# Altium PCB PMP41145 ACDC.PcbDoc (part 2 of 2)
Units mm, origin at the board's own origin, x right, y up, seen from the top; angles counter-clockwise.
Board outline 48.82 x 27.36 mm, 2 copper layers (Top Layer, Bottom Layer), stack 1.016 mm thick; 61 components, 40 nets, 174 pads, 389 vias.
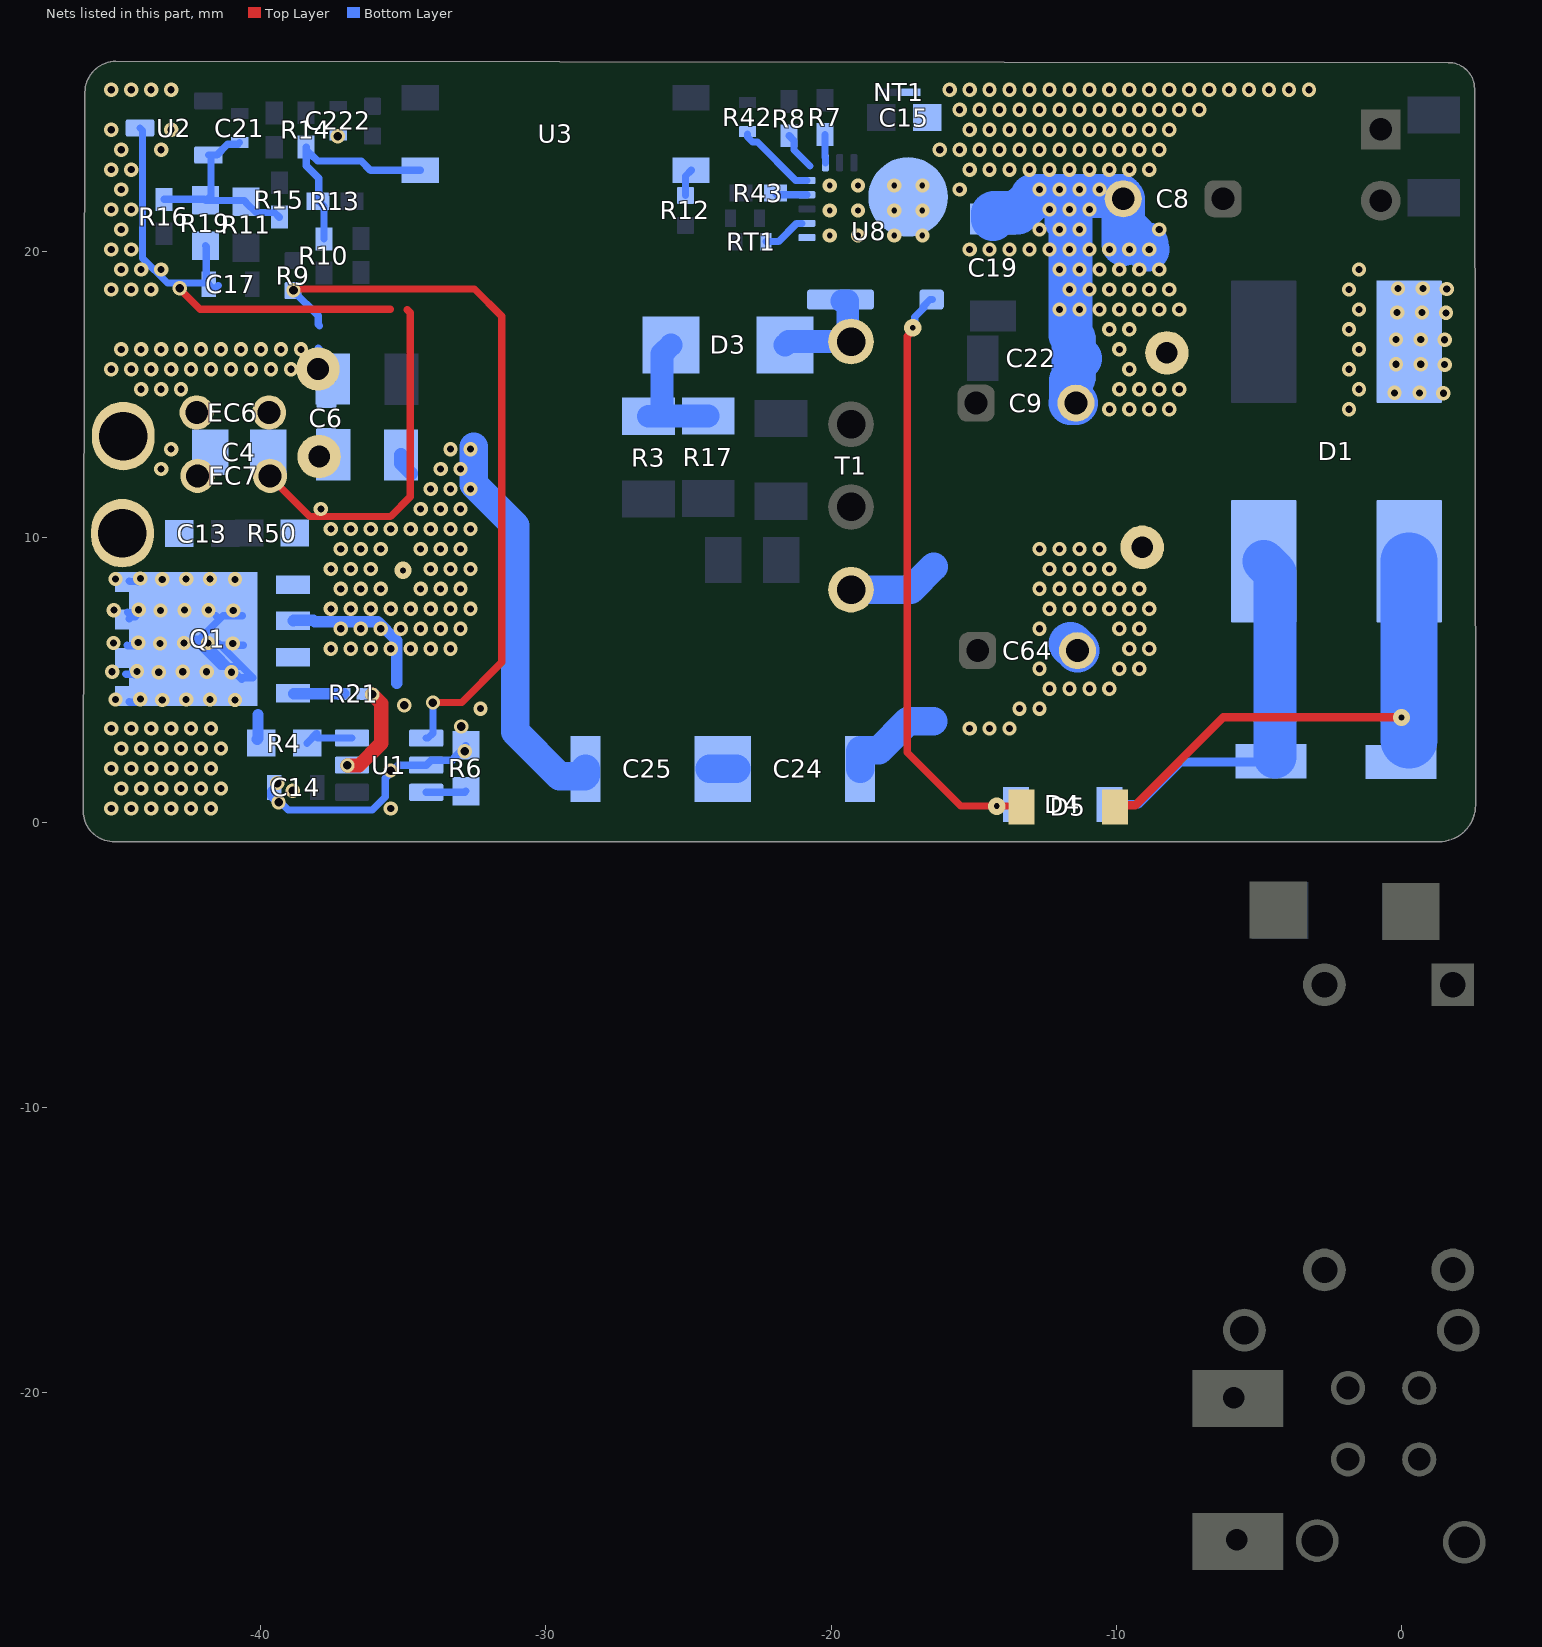
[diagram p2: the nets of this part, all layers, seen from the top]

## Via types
v1: diameter 0.5, hole 0.25, Top Layer to Bottom Layer, 301 vias
v2: diameter 0.5, hole 0.25, Top Layer to Bottom Layer, tented both sides, 45 vias
v3: diameter 0.61, hole 0.203, Top Layer to Bottom Layer, tented both sides, 16 vias
v4: diameter 0.5, hole 0.3, Top Layer to Bottom Layer, tented both sides, 15 vias
v5: diameter 0.5, hole 0.2, Top Layer to Bottom Layer, tented both sides, 12 vias

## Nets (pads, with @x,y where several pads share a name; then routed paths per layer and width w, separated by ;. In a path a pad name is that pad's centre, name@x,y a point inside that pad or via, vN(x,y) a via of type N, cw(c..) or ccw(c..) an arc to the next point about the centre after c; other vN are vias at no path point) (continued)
NetC21_1: C21.1 R11.1 R15.2 R16.1 R19.2 U2.2 | length 7.3
  Bottom Layer w0.254: R16.1@-43.395,21.84 -43.385,21.85 -41.975,21.85 R19.2@-41.931,21.806 ; R19.2@-41.94,21.815 R19.2@-41.931,21.806 ; R19.2@-41.907,21.806 -41.743,21.97 U2.2@-41.743,23.396 ; U2.2@-41.833,23.396 U2.2@-41.743,23.396 ; C21.1@-40.74,23.837 -40.803,23.774 -41.166,23.774 -41.543,23.396 U2.2@-41.743,23.396 ; R15.2@-39.352,21.217 -39.517,21.382 -40.167,21.382 -40.515,21.73 R11.1@-40.515,21.755 -40.566,21.806 R19.2@-41.931,21.806
NetC24_2: C24.2 C25.1 | length 0.9
  Bottom Layer w1: C25.1@-24.261,1.871 C24.2@-23.331,1.871
NetD1_2: D1.2 D4.2 pad.N@-4.575,2.145 | length 13
  Bottom Layer w0.3: D4.2@-10.242,0.63 -9.225,0.63 -7.74,2.115 pad.N@-4.905,2.115
  Bottom Layer w1.5: D1.2@-4.83,9.155 -4.43,8.755 pad.N@-4.43,2.29
NetD1_3: D1.3 D5.2 pad.N@-0.015,2.115 | length 17.6
  Top Layer w0.2: v3@-0.015,3.69 v3(0,3.675)
  Top Layer w0.3: D5.2@-10.048,0.54 -9.988,0.6 -9.33,0.6 -6.24,3.69 v3@-0.075,3.69
  Bottom Layer w2: 0.27,2.88 D1.3@0.27,9.155
NetD3_1: D3.1 R3.1 R17.1 | length 4.9
  Bottom Layer w0.8: R3.1@-26.401,14.239 -26.175,14.239 -25.925,14.489 -25.925,16.43 D3.1@-25.614,16.74 ; R3.1@-26.24,14.239 -26.232,14.247 -24.314,14.247 R17.1@-24.306,14.255
NetD3_2: D3.2 T1.4 U8.2 | length 3.7
  Bottom Layer w0.8: D3.2@-21.614,16.74 -21.489,16.865 T1.4@-19.68,16.865 ; U8.2@-19.623,18.28 -19.414,18.28 -19.414,16.974 T1.4@-19.3,16.86
NetD4_1: D4.1 D5.1 U8.1 | length 21.8
  Top Layer w0.254: v3(-17.135,17.34) -17.135,17.244 -17.33,17.049 -17.33,2.449 -15.451,0.57 -13.353,0.57 D5.1@-13.323,0.54
  Bottom Layer w0.254: v3(-17.135,17.34) -17.067,17.408 -17.067,17.718 -16.753,18.032 -16.753,18.107 -16.53,18.33 U8.1@-16.455,18.33 ; v3(-14.19,0.57) -13.577,0.57 D4.1@-13.517,0.63
NetF1_2: 
NetQ1_4: Q1.4 R21.1 | length 1.8
  Bottom Layer w0.4: Q1.4@-38.845,4.505 R21.1@-37.084,4.505
NetR4_2: R4.2 U1.6 | length 2.8
  Bottom Layer w0.254: U1.6@-36.798,2.955 -38.001,2.955 -38.032,2.985 R4.2@-38.032,3.12 ; R4.2@-38.374,2.777 R4.2@-38.032,3.12 ; R4.2@-38.374,2.777 R4.2@-38.032,3.12 ; R4.2@-38.374,2.777 R4.2@-38.032,3.12
NetR6_2: R6.2 U1.3 | length 1.4
  Bottom Layer w0.254: U1.3@-34.198,1.055 -32.849,1.055 R6.2@-32.807,1.097
NetR7_2: R7.2 U8.9 | length 1
  Bottom Layer w0.254: R7.2@-20.21,24.12 -20.21,23.313 -20.198,23.301 U8.9@-20.198,23.13
NetR8_2: R8.2 U8.8 | length 1.4
  Bottom Layer w0.254: R8.2@-21.47,24.075 -21.297,23.902 -21.297,23.579 U8.8@-20.736,23.018
NetR10_1: R10.1 R13.1 R14.2 U3.1 | length 7.9
  Bottom Layer w0.254: R14.2@-38.415,23.685 -38.415,23.585 -38.242,23.412 -38.224,23.412 -38.002,23.19 -36.475,23.19 -36.155,22.87 U3.1@-34.405,22.87 ; R14.2@-38.4,23.67 -38.4,23.025 -37.963,22.588 -37.963,21.812 R13.1@-37.995,21.78 -37.958,21.78 -37.785,21.607 R10.1@-37.785,20.46
NetR12_2: R12.2 U3.4 | length 1
  Bottom Layer w0.254: R12.2@-25.108,21.982 -25.108,22.667 U3.4@-24.905,22.87
NetR21_2: R21.2 U1.5 | length 3.3
  Top Layer w0.5: v4(-36.96,1.995) -36.555,1.995 -35.775,2.775 -35.775,4.17 v4(-36.09,4.485)
NetR42_2: R42.2 U8.7 | length 2.8
  Bottom Layer w0.254: R42.2@-22.93,24.128 -22.93,24.028 -22.757,23.855 -22.584,23.855 -21.236,22.507 -20.85,22.507 U8.7@-20.848,22.505
NetR43_2: R43.2 U8.6 | length 1.1
  Bottom Layer w0.254: R43.2@-21.953,22.065 -21.895,22.007 -20.85,22.007 U8.6@-20.848,22.005
NetRT1_2: RT1.2 U8.4 | length 1.5
  Bottom Layer w0.254: RT1.2@-22.284,20.363 -21.846,20.363 -21.206,21.003 U8.4@-21.021,21.003
Neture: 
PGND: C8.2 C9.2 C15.2 C19.2 C22.2 C24.1 C64.2 D1.4 NT1.1 pad.8 T1.1 U8.3 U8.12 | length 23.7
  Bottom Layer w1: T1.1@-19.3,7.997 T1.1@-19.3,8.16 ; C24.1@-18.981,1.871 -18.981,2.496 -18.956,2.521 -18.331,2.521 -17.312,3.54 -16.425,3.54 ; T1.1@-18.981,8.16 -17.207,8.16 -16.396,8.97
  Bottom Layer w1.54: C19.2@-14.32,21.155 -14.32,21.345 -14.29,21.375 -13.454,21.375 -12.942,21.887 ; -12.942,21.965 -11.446,21.965 ; -12.142,21.887 -11.525,21.887 -11.446,21.965 ; -11.742,21.087 -11.6,21.087 ; C64.2@-11.6,6.262 C64.2@-11.359,6.021 ; C9.2@-11.413,14.699 -11.6,14.699 -11.587,14.713 -11.587,15.487 -11.497,15.577 -11.497,16.239 C22.2@-11.467,16.269 ; C22.2@-11.277,16.269 C22.2@-11.467,16.269 ; -9.742,20.287 -9.742,20.922 -9.755,20.935 ; v1@-8.942,20.122 v1@-8.942,20.287 ; v1@-8.9,20.08 -9.755,20.935 ; -11.6,21.087 -11.6,21.811 -11.446,21.965 ; -11.6,21.087 -11.6,17.087 -11.497,16.983 -11.497,16.299 C22.2@-11.467,16.269 ; -11.446,21.965 -9.855,21.965 C8.2@-9.755,21.865 -9.755,20.935
  other v1: -15.142,3.287 -14.442,3.287 -13.742,3.287 -13.392,3.987 -12.692,3.987 -12.342,4.687 -11.642,4.687 -10.942,4.687 -10.242,4.687 -12.692,5.387 -9.892,5.387 -9.192,5.387 -9.542,6.087 -8.842,6.087 -12.692,6.787 -9.892,6.787 -9.192,6.787 -12.342,7.487 -11.642,7.487 -10.942,7.487 -10.242,7.487 -9.542,7.487 -8.842,7.487 -12.692,8.187 -11.992,8.187 -11.292,8.187 -10.592,8.187 -9.892,8.187 -9.192,8.187 -12.342,8.887 -11.642,8.887 -10.942,8.887 -10.242,8.887 -12.692,9.587 -11.992,9.587 -11.292,9.587 -10.592,9.587 -10.242,14.487 -9.542,14.487 -8.842,14.487 -8.142,14.487 -1.842,14.487 -9.892,15.187 -9.192,15.187 -8.492,15.187 -7.792,15.187 -1.492,15.187 -9.542,15.887 -1.842,15.887 -9.892,16.587 -1.492,16.587 -10.242,17.287 -9.542,17.287 -1.842,17.287 -11.992,17.987 -11.292,17.987 -10.592,17.987 -9.892,17.987 -9.192,17.987 -8.492,17.987 -7.792,17.987 -1.492,17.987 -11.642,18.687 -10.942,18.687 -10.242,18.687 -9.542,18.687 -8.842,18.687 -8.142,18.687 -1.842,18.687 -11.992,19.387 -11.292,19.387 -10.592,19.387 -9.892,19.387 -9.192,19.387 -8.492,19.387 -1.492,19.387 -15.142,20.087 -14.442,20.087 -13.742,20.087 -13.042,20.087 -12.342,20.087 -11.642,20.087 -10.942,20.087 -10.242,20.087 -9.542,20.087 -8.842,20.087 -12.692,20.787 -11.992,20.787 -11.292,20.787 -8.492,20.787 -12.342,21.487 -11.642,21.487 -10.942,21.487 -15.492,22.187 -12.692,22.187 -11.992,22.187 -11.292,22.187 -10.592,22.187 -15.142,22.887 -14.442,22.887 -13.742,22.887 -13.042,22.887 -12.342,22.887 -11.642,22.887 -10.942,22.887 -10.242,22.887 -9.542,22.887 -8.842,22.887 -16.192,23.587 -15.492,23.587 -14.792,23.587 -14.092,23.587 -13.392,23.587 -12.692,23.587 -11.992,23.587 -11.292,23.587 -10.592,23.587 -9.892,23.587 -9.192,23.587 -8.492,23.587 -15.142,24.287 -14.442,24.287 -13.742,24.287 -13.042,24.287 -12.342,24.287 -11.642,24.287 -10.942,24.287 -10.242,24.287 -9.542,24.287 -8.842,24.287 -8.142,24.287 -15.492,24.987 -14.792,24.987 -14.092,24.987 -13.392,24.987 -12.692,24.987 -11.992,24.987 -11.292,24.987 -10.592,24.987 -9.892,24.987 -9.192,24.987 -8.492,24.987 -7.792,24.987 -7.092,24.987 -15.842,25.687 -15.142,25.687 -14.442,25.687 -13.742,25.687 -13.042,25.687 -12.342,25.687 -11.642,25.687 -10.942,25.687 -10.242,25.687 -9.542,25.687 -8.842,25.687 -8.142,25.687 -7.442,25.687 -6.742,25.687 -6.042,25.687 -5.342,25.687 -4.642,25.687 -3.942,25.687 -3.242,25.687
  other v2: -0.24,15.06 0.63,15.06 1.47,15.045 1.515,16.05 -0.195,16.065 0.675,16.065 1.515,16.92 -0.195,16.935 0.675,16.935 -0.15,17.88 0.72,17.88 1.56,17.865 -0.12,18.72 0.75,18.72 1.59,18.705
  other v5: -20.048,20.58 -19.058,20.58 -17.788,20.58 -16.798,20.58 -20.048,21.455 -19.058,21.455 -17.788,21.455 -16.798,21.455 -20.048,22.33 -19.058,22.33 -17.788,22.33 -16.798,22.33
SGND: C4.2 C6.2 C14.2 C17.1 C25.2 C222.1 EC6.2 EC7.2 pad.9@-37.95,12.825 pad.N@-35.08,12.88 pad.N@-37.455,12.892 Q1.1 Q1.2 Q1.3 R6.1 R19.1 R50.1 U1.2 U2.3 | length 58.3
  Top Layer w0.254: v4@-42.856,18.72 -42.131,17.995 -35.455,17.995 ; EC7.2@-39.675,12.15 -39.675,12.12 -38.28,10.725 -35.445,10.725 -34.755,11.415 -34.755,17.865 -34.86,17.97
  Bottom Layer w0.254: U2.3@-44.233,24.346 -44.143,24.256 -44.143,19.783 -43.272,18.912 -41.856,18.912 C17.1@-41.814,18.87 -41.907,18.963 -41.907,20.182 R19.1@-41.94,20.215 ; C17.1@-41.814,18.858 -41.632,18.676 -41.487,18.822 ; C14.2@-39.533,1.223 -39.653,1.103 -39.653,0.913 v4@-39.41,0.67 ; v4(-39.375,0.705) v4@-39.41,0.67 ; R6.1@-32.807,2.697 -32.807,2.672 -33.217,2.262 -33.217,2.247 -33.286,2.178 -34.025,2.178 U1.2@-34.198,2.005 -35.179,2.005 -35.636,1.548 -35.636,0.887 -36.093,0.43 -39.033,0.43 -39.273,0.67 v4@-39.41,0.67
  Bottom Layer w0.4: Q1.2@-38.865,7.065 -38.843,7.087 -38.153,7.087 -38.101,7.035 -35.895,7.035 -35.235,6.375 -35.235,4.871
  Bottom Layer w0.5: pad.N@-35.08,12.88 -35.08,12.58 pad.N@-34.73,12.23
  Bottom Layer w1: v1@-32.535,13.17 -32.535,11.85 -31.08,10.395 -31.08,3.18 -29.52,1.62 -28.636,1.62 -28.611,1.645 C25.2@-28.611,1.871
  other v1: -35.442,0.487 -32.292,3.987 -37.542,6.087 -36.842,6.087 -36.142,6.087 -35.442,6.087 -34.742,6.087 -34.042,6.087 -33.342,6.087 -37.192,6.787 -36.492,6.787 -35.792,6.787 -35.092,6.787 -34.392,6.787 -33.692,6.787 -32.992,6.787 -37.542,7.487 -36.842,7.487 -36.142,7.487 -35.442,7.487 -34.742,7.487 -34.042,7.487 -33.342,7.487 -32.642,7.487 -37.192,8.187 -36.492,8.187 -35.792,8.187 -34.392,8.187 -33.692,8.187 -32.992,8.187 -37.542,8.887 -36.842,8.887 -36.142,8.887 -34.042,8.887 -33.342,8.887 -32.642,8.887 -37.192,9.587 -36.492,9.587 -35.792,9.587 -34.392,9.587 -33.692,9.587 -32.992,9.587 -37.542,10.287 -36.842,10.287 -36.142,10.287 -35.442,10.287 -34.742,10.287 -34.042,10.287 -33.342,10.287 -32.642,10.287 -37.892,10.987 -34.392,10.987 -33.692,10.987 -32.992,10.987 -34.042,11.687 -33.342,11.687 -32.642,11.687 -33.692,12.387 -32.992,12.387 -33.342,13.087 -32.642,13.087 -45.242,18.687 -44.542,18.687 -43.842,18.687 -44.892,19.387 -44.192,19.387 -43.492,19.387 -45.242,20.087 -44.542,20.087 -44.892,20.787 -45.242,21.487 -44.542,21.487 -44.892,22.187 -45.242,22.887 -44.542,22.887 -44.892,23.587 -43.492,23.587 -45.242,24.287 -43.142,24.287 -45.242,25.687 -44.542,25.687 -43.842,25.687 -43.142,25.687
  other v3: -35.01,8.835
  other v4: -38.88,1.11 -39.417,1.38 -35.445,1.815 -32.85,2.49 -32.97,3.36 -34.965,4.11 -42.838,18.732 -37.303,24.057
VO_ACDC: C4.1 C6.1 EC6.1 EC7.1 pad.5@-44.82,13.545 pad.9@-37.995,15.9 pad.N@-37.475,15.545 R9.2 U1.1 | length 27.2
  Top Layer w0.254: v4(-38.85,18.66) -38.812,18.698 -38.219,18.698 -38.212,18.705 -32.505,18.705 -31.545,17.745 -31.545,5.61 -32.955,4.2 v4(-33.96,4.2)
  Bottom Layer w0.254: v4(-38.85,18.66) R9.2@-38.865,18.645 -37.98,17.76 -37.98,17.46 -37.935,17.415 ; pad.9@-37.98,16.62 -37.948,16.588 -37.948,16.018 pad.N@-37.475,15.545 ; U1.1@-34.198,2.955 -34.133,2.955 -33.96,3.128 v4(-33.96,4.2)
  other v1: -43.492,12.387 -43.142,13.087 -44.192,15.187 -43.492,15.187 -42.792,15.187 -45.242,15.887 -44.542,15.887 -43.842,15.887 -43.142,15.887 -42.442,15.887 -41.742,15.887 -41.042,15.887 -40.342,15.887 -39.642,15.887 -38.942,15.887 -44.892,16.587 -44.192,16.587 -43.492,16.587 -42.792,16.587 -42.092,16.587 -41.392,16.587 -40.692,16.587 -39.992,16.587 -39.292,16.587 -38.592,16.587
VSR_SW: C13.1 pad.5@-44.85,10.14 Q1.5 Q1.6 Q1.7 Q1.8 Q1.9 R4.1 | length 14.5
  Bottom Layer w0.254: -44.73,5.205 -44.715,5.19 -44.46,5.19 Q1.9@-44.445,5.175 ; -44.685,6.21 -44.67,6.195 -44.415,6.195 Q1.9@-44.4,6.18 ; Q1.7@-44.67,7.365 -44.655,7.35 -44.4,7.35 Q1.9@-44.385,7.335 ; Q1.9@-44.61,4.23 -44.595,4.215 -44.34,4.215 Q1.9@-44.325,4.2 ; Q1.9@-44.61,7.135 -44.532,7.213 -44.402,7.213 Q1.9@-44.355,7.26 ; Q1.9@-44.61,8.46 -44.595,8.445 -44.34,8.445 Q1.9@-44.325,8.43 ; Q1.9@-41.565,7.245 Q1.9@-41.445,7.125 ; Q1.9@-41.52,6.21 -41.466,6.264 Q1.9@-40.665,5.464 ; Q1.9@-40.665,5.01 -40.665,5.015 Q1.9@-40.723,5.073 ; Q1.9@-40.65,7.245 -41.325,7.245 Q1.9@-41.445,7.125 ; Q1.9@-40.605,6.21 -41.466,6.21 Q1.9@-41.86,6.21 ; Q1.9@-42.365,6.43 Q1.9@-41.399,5.464 ; Q1.9@-42.365,6.43 -42.14,6.43 Q1.9@-41.445,7.125 ; Q1.9@-42.365,6.43 Q1.9@-42.145,6.21 ; Q1.9@-42.145,6.21 -41.58,5.645 Q1.9@-41.399,5.464 ; Q1.9@-42.145,6.21 Q1.9@-41.86,6.21 ; Q1.9@-41.86,6.21 -41.58,5.93 Q1.9@-41.114,5.464 ; Q1.9@-41.399,5.464 Q1.9@-40.665,5.464 ; Q1.9@-41.399,5.464 Q1.9@-41.114,5.464 ; Q1.9@-41.114,5.464 Q1.9@-40.665,5.464 ; Q1.9@-41.114,5.464 Q1.9@-40.723,5.073 ; Q1.9@-40.723,5.073 -40.274,5.073 Q1.9@-40.665,5.464
  Bottom Layer w0.4: R4.1@-40.116,2.919 -40.095,2.94 -40.095,3.78
  other v1: -45.242,0.487 -44.542,0.487 -43.842,0.487 -43.142,0.487 -42.442,0.487 -41.742,0.487 -44.892,1.187 -44.192,1.187 -43.492,1.187 -42.792,1.187 -42.092,1.187 -41.392,1.187 -45.242,1.887 -44.542,1.887 -43.842,1.887 -43.142,1.887 -42.442,1.887 -41.742,1.887 -44.892,2.587 -44.192,2.587 -43.492,2.587 -42.792,2.587 -42.092,2.587 -41.392,2.587 -45.242,3.287 -44.542,3.287 -43.842,3.287 -43.142,3.287 -42.442,3.287 -41.742,3.287
  other v2: -43.455,4.29 -40.905,4.29 -45.09,4.305 -44.22,4.32 -42.615,4.305 -41.775,4.305 -45.21,5.28 -43.575,5.265 -42.735,5.28 -41.895,5.28 -41.025,5.265 -44.34,5.295 -43.53,6.27 -40.98,6.27 -45.165,6.285 -44.295,6.3 -42.69,6.285 -41.85,6.285 -45.15,7.44 -43.515,7.425 -42.675,7.44 -41.835,7.44 -40.965,7.425 -44.28,7.455 -45.09,8.535 -43.455,8.52 -42.615,8.535 -41.775,8.535 -40.905,8.52 -44.22,8.55
pads on no net: C1.1 C1.2 F1.1 F1.2 F3.1 F3.2 L2.1 L2.2 L2.3 L2.4 L5.1 L5.2 L5.3 L5.4 T1.2
copper on no net: | length 82
  Top Layer w1: -4.395,-3.135 -4.38,-3.12 ; 0.465,-3.135 0.727,-3.397
  Top Layer w1.5: -6.06,-25.185 -2.955,-25.185 ; -5.745,-20.21 -5.155,-20.21 -3.06,-22.305 -1.89,-22.305 ; -5.505,-17.805 -5.505,-11.115 -2.7,-8.31 -2.7,-5.695 ; -5.13,-17.79 -3.92,-17.79 -1.875,-19.835 ; -2.88,-15.735 -2.28,-15.735 -1.77,-16.245 -0.21,-17.805 1.995,-17.805 ; v3@0.345,-3.54 0.345,-4.395 1.62,-5.67 ; 0.625,-19.835 0.625,-19.115 1.59,-18.15 1.665,-18.15 1.875,-17.94 ; 0.675,-22.275 2.205,-23.805 2.205,-25.245
  Bottom Layer w1.5: -5.73,-20.21 -5.14,-20.21 -2.97,-22.38 -2.025,-22.38 ; -5.595,-17.745 -3.965,-17.745 -1.875,-19.835 ; -5.295,-25.26 -5.22,-25.185 -2.955,-25.185 ; v3(-4.44,-3.525) -4.26,-3.345 -4.26,-3.09 ; v3@-4.44,-3.34 -4.51,-3.34 -4.51,-4.435 -5.49,-5.415 -5.49,-7.09 -5.49,-8.56 1.62,-15.67 ; -2.7,-15.695 -2.365,-15.695 -0.72,-17.34 -0.315,-17.745 1.965,-17.745 ; v3@0.345,-3.553 0.345,-4.24 1.8,-5.695 ; 0.625,-22.335 2.02,-23.73 2.115,-23.825 2.115,-25.2 ; 0.625,-19.835 0.625,-19.49 2.07,-18.045
  other v3: 0.405,-3.885 0.285,-3.39 0.795,-2.94 -4.035,-2.85 0,-2.805 -4.755,-2.775

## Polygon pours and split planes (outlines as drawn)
NetC3_2 on Bottom Layer "BOTTOM_LAYER_NETC3_2_P205" (solid, remove dead copper, pour order 205): -20.03,14.85 -16.145,14.85 -15.335,15.66 -15.335,18.315 -15.35,18.33 -13.43,18.33 -13.415,18.315 -13.415,14.91 -15.2,13.125 -20.03,13.125 -20.03,14.865
VO_ACDC on Bottom Layer "BOTTOM_LAYER_VO_ACDC_P261" (solid, remove dead copper, pour order 261): -37.14,17.445 -36.84,17.145 -36.84,14.535 -37.065,14.31 -38.025,14.31 -38.97,15.255 -40.92,15.255 -40.98,15.315 -40.98,17.445
VO_ACDC on Bottom Layer "BOTTOM_LAYER_VO_ACDC_P255" (solid, remove dead copper, pour order 255): -40.965,17.43 -40.965,11.43 -45.15,11.43 -45.15,17.43
VO_ACDC on Bottom Layer "BOTTOM_LAYER_VO_ACDC_P253" (solid, remove dead copper, pour order 253): -37.155,17.52 -36.855,17.22 -36.855,14.61 -37.08,14.385 -38.04,14.385 -38.985,15.33 -40.935,15.33 -40.995,15.39 -40.995,17.52
VSR_SW on Bottom Layer "BOTTOM_LAYER_VSR_SW_P239" (solid, remove dead copper, pour order 239): -46.031,11.37 -39.75,11.37 -39.75,3.39 -40.776,3.39 -40.798,-0.375 -46.031,-0.375
PGND on Bottom Layer "BOTTOM_LAYER_PGND_P238" (solid, remove dead copper, pour order 238): -25.595,26.644 -25.595,5.055 -17.585,5.058 -17.585,2.031 -7.23,2.031 -7.23,13.845 2.5,13.845 2.5,26.644
SGND on Bottom Layer "BOTTOM_LAYER_SGND_P250" (solid, remove dead copper, pour order 250): -40.005,1.83 -40.005,-0.33 -31.74,-0.33 -31.74,5.145 -35.565,5.145 -35.565,2.46 -36.195,1.83
VO_ACDC on Bottom Layer "BOTTOM_LAYER_VO_ACDC_P242" (solid, remove dead copper, pour order 242): -40.95,17.505 -40.95,11.505 -46.031,11.505 -46.031,17.505
SGND on Bottom Layer "BOTTOM_LAYER_SGND_P241" (solid, remove dead copper, pour order 241): -45.78,17.94 -33.81,17.94 -33.81,26.644 -45.78,26.644
SGND on Bottom Layer "BOTTOM_LAYER_SGND_P206" (solid, pour order 206): -38.446,14.19 -39.24,15.021 -40.515,15.021 -40.515,10.995 -39.57,10.995 -39.57,5.025 -31.755,5.025 -31.755,14.19
APGND on Bottom Layer "BOTTOM_LAYER_APGND_P208" (solid, remove dead copper, pour order 208): -23.865,26.37 -23.865,20.055 -22.514,20.055 -22.514,22.125 -21.039,22.905 -19.154,22.905 -19.128,25.189 -17.521,25.2 -17.521,26.37
no net on Bottom Layer "BOTTOM_LAYER_NONET_P237" (solid, remove dead copper, shelved, pour order 237): -57.865,21.931 -56.42,23.376 -56.42,23.441 -56.143,23.441 -55.953,23.251 -55.953,21.705 -56.881,21.705 -57.168,21.419
no net on Bottom Layer "BOTTOM_LAYER_NONET_P233" (solid, remove dead copper, shelved, pour order 233): -21.741,21.25 -21.741,25.72 -21.674,25.787 -19.436,25.787 -19.341,25.691 -19.341,24.325 -18.599,24.325 -18.556,24.282 -18.556,21.193 -21.725,21.193 -21.725,25.757 -21.147,25.757 -21.133,25.771 -21.711,25.771 -21.711,24.293 -18.584,21.165
no net on Top Layer "Default Coverlay 2 Top" (split plane): -62.881,32.25 -61.865,32.25 -61.865,-5 -62.864,-5
no net on Top Layer "Default Coverlay 2 Bottom" (split plane): -62.881,32.25 -61.865,32.25 -61.865,-5 -62.864,-5
SGND on Top Layer "TOP_LAYER_SGND_P257" (solid, remove dead copper, pour order 257): -40.44,17.55 -40.44,14.1 -40.44,10.965 -39,10.965 -39,5.265 -31.62,5.265 -31.62,17.55
SGND on Top Layer "TOP_LAYER_SGND_P260" (solid, remove dead copper, pour order 260): -46.031,17.82 -33.375,17.82 -33.375,26.644 -46.031,26.644
VO_ACDC on Top Layer "TOP_LAYER_VO_ACDC_P236" (solid, remove dead copper, pour order 236): -37.2,17.49 -36.9,17.19 -36.9,14.58 -37.125,14.355 -38.085,14.355 -39.03,15.3 -40.98,15.3 -41.04,15.36 -41.04,17.49
VO_ACDC on Top Layer "TOP_LAYER_VO_ACDC_P259" (solid, remove dead copper, pour order 259): -40.785,17.475 -40.785,11.385 -46.036,11.385 -46.036,17.475
VSR_SW on Top Layer "TOP_LAYER_VSR_SW_P258" (solid, remove dead copper, pour order 258): -46.031,11.34 -39.15,11.34 -39.15,3.36 -40.821,3.36 -40.842,-0.18 -46.031,-0.18
SGND on Top Layer "TOP_LAYER_SGND_P256" (solid, remove dead copper, pour order 256): -40.245,1.83 -40.245,-0.24 -31.305,-0.24 -31.305,5.089 -35.25,5.153 -35.25,2.82 -36.24,1.83
PGND on Top Layer "TOP_LAYER_PGND_P246" (solid, remove dead copper, pour order 246): -25.951,26.644 -25.951,10.26 -25.501,9.81 -16.966,9.81 -16.966,2.58 -7.905,2.58 2.564,2.58 2.564,26.644

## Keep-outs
Keep-Out Layer:
  text ".Layer_Name" at -87.209,-70.556 h1.52

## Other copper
Top Layer:
  pour cut-out: -26.09,19.17 -26.09,6.884 -17.825,6.884 -17.825,19.17
  text ".Layer_Name" at -87.209,-70.556 h1.52
Bottom Layer:
  pour cut-out: -20.195,12.255 -20.195,4.905 -17.765,4.905 -17.765,12.255
  pour cut-out: -40.74,1.875 -40.74,0.225 -39.96,0.225 -39.96,1.875
  pour cut-out: -26.146,19.215 -26.146,4.965 -20.225,4.965 -20.225,19.215
  text ".Layer_Name" at -87.209,-70.556 h1.52

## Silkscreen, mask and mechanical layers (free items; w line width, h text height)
Top Overlay:
  text ".Layer_Name" at -87.209,-70.556 h1.52
Bottom Overlay:
  text ".Layer_Name" at -87.209,-70.556 h1.52
Top Paste:
  text ".Layer_Name" at -87.209,-70.556 h1.52
Bottom Paste:
  text ".Layer_Name" at -87.209,-70.556 h1.52
Top Solder:
  region: 1.92,10.468 -10.29,10.468 -10.29,6.81 1.92,6.81
  region: 1.935,7.515 1.935,19.83 -2.13,19.83 -2.13,7.515
  region: -8.34,19.935 -8.34,26.162 -20.7,26.162 -20.7,19.935
  rectangle: -35.84,17.94 -35.19,18.195
  region: -32.22,5.505 -32.22,10.614 -38.652,10.614 -38.652,5.505
  region: -32.16,7.926 -32.16,17.22 -35.022,17.22 -35.022,7.926
  region: -39.48,8.352 -39.48,10.41 -43.535,10.41 -43.535,8.352
  region: -39.495,3.825 -39.495,8.85 -45.585,8.85 -45.585,3.825
  region: -41.1,0.135 -41.1,4.005 -45.6,4.005 -45.6,0.135
  rectangle: -45.705,15.48 -37.515,17.34
  text ".Layer_Name" at -87.209,-70.556 h1.52
  text ".Layer_Name" at -87.209,-70.556 h1.52
Bottom Solder:
  region: -8.775,4.824 -8.775,13.2 -12.692,13.2 -12.692,4.824
  region: -8.16,12.909 -8.16,20.439 -12.077,20.439 -12.077,12.909
  rectangle: -2.444,14.085 2.115,19.74
  rectangle: -10.23,23.88 -2.7,26.19
  rectangle: -38.97,5.415 -32.16,10.65
  rectangle: -45.66,15.465 -37.59,17.276
  rectangle: -45.51,0 -40.995,8.925
  rectangle: -15.45,20.04 -8.22,23.82
  rectangle: -15.435,23.145 -7.905,26.175
  lines w1.2: -3.69,21.48 -3.69,24.345 ; -3.555,21.27 -1.74,19.455 -1.74,19.275
  text ".Layer_Name" at -87.209,-70.556 h1.52
Drill Guide:
  text ".Layer_Name" at -87.209,-70.556 h1.52
M1 Board Outline:
  lines w0.127: -46.155,0.27 -46.1,25.595 cw(c-45.075,25.595) -45.075,26.62 1.643,26.58 cw(c1.643,25.723) 2.5,25.723 2.535,0.602 cw(c1.318,0.602) 1.318,-0.615 ; -46.155,0.387 ccw(c-45.155,0.387) -45.155,-0.613 ; -45.183,-0.615 1.29,-0.615 ; -8.04,-5.83 -8.04,-27.565 2.625,-27.565 2.625,-5.825 2.622,-5.822 0.945,-5.822 0.945,-3.6 ; -8.038,-5.83 -5.895,-5.83 -5.895,-3.6 0.93,-3.6 ; -33.467,0 -33.467,0
  text ".Layer_Name" at -87.209,-70.556 h1.52
M2 Board Dimensions:
  rectangle: -101.865,-55.735 -98.69,-52.56
  rectangle: -98.69,-58.91 -89.165,-55.735
  lines w0.178: -101.865,-55.735 -76.465,-55.735 ; -98.69,-58.91 -98.69,-52.56 ; -95.515,-58.91 -95.515,-52.56 ; -89.165,-58.91 -89.165,-52.56 ; -82.815,-58.91 -82.815,-52.56 ; -101.865,-58.91 -76.465,-58.91 -76.465,-52.56 -101.865,-52.56 -101.865,-58.91
  text ".Layer_Name" at -87.209,-70.556 h1.52
M3 3D STEP Top:
  text ".Layer_Name" at -87.209,-70.556 h1.52
M4 3D STEP Bottom:
  text ".Layer_Name" at -87.209,-70.556 h1.52
M5 Assembly Top:
  lines w0.254: -109.282,-72.376 58.358,-72.376 ; -109.282,-67.212 58.409,-67.212 ; -109.282,-62.047 -109.282,-77.541 -7.555,-77.541 58.409,-77.541 58.409,-62.047 -109.269,-62.047 -109.269,-77.541 -69.251,-77.541 ; -46.671,-77.541 -46.671,-62.047 ; -14.489,-67.212 -14.489,-62.047 ; 6.847,-67.212 6.847,-62.047 ; 22.646,-77.706 22.646,-72.554
  text "COMPONENTS MARKED 'DNP' SHOULD NOT BE POPULATED." at -72.566,-56.84 h1.52
  text "ASSEMBLY VARIANT:" at -72.579,-59.774 h1.52
  text ".VariantName" at -46.264,-59.774 h1.52
  text "PCB VIEWED FROM TOP SIDE" at -107.669,-65.404 h1.52
  text "BOARD #:" at -44.766,-65.404 h1.52
  text ".PRJ_Number" at -30.91,-65.404 h1.52
  text "REV:" at -9.46,-65.404 h1.52
  text ".PCB_Rev" at -2.056,-65.404 h1.52
  text "SVN REV:" at 11.825,-65.404 h1.52
  text ".VersionControl_RevNumber" at 24.678,-65.404 h1.52
  text "TID #:" at -44.766,-70.569 h1.52
  text ".TID" at -30.91,-70.569 h1.52
  text "PLOT NAME =" at -107.669,-75.784 h1.52
  text ".plot_File_Name" at -87.209,-75.784 h1.52
  text "GENERATED    :" at -44.715,-75.784 h1.52
  text ".Print_Date" at -22.63,-75.784 h1.52
  text ".Print_Time" at -4.113,-75.784 h1.52
  text "TEXAS INSTRUMENTS" at 28.005,-75.784 h1.52
M6 Assembly Bottom:
  lines w0.254: -109.295,-67.224 58.396,-67.224 ; -109.244,-72.389 58.396,-72.389 ; -73.531,-77.719 -73.531,-72.567 ; -57.733,-67.224 -57.733,-62.06 ; -36.397,-67.224 -36.397,-62.06 ; -4.215,-77.554 -4.215,-62.06 ; 18.366,-77.554 58.384,-77.554 58.384,-62.06 -109.295,-62.06 -109.295,-77.554 -43.331,-77.554 58.396,-77.554 58.396,-62.06
  text "COMPONENTS MARKED 'DNP' SHOULD NOT BE POPULATED." at 53.126,-56.827 h1.52
  text ".VariantName" at 26.608,-59.774 h1.52
  text "ASSEMBLY VARIANT:" at 52.999,-59.774 h1.52
  text ".VersionControl_RevNumber" at -75.563,-65.417 h1.52
  text "SVN REV:" at -62.711,-65.417 h1.52
  text ".PCB_Rev" at -48.83,-65.417 h1.52
  text "REV:" at -41.426,-65.417 h1.52
  text ".PRJ_Number" at -19.975,-65.417 h1.52
  text "BOARD #:" at -6.12,-65.417 h1.52
  text "PCB VIEWED FROM BOTTOM SIDE" at 56.783,-65.417 h1.52
  text ".TID" at -19.975,-70.581 h1.52
  text "TID #:" at -6.12,-70.581 h1.52
  text "TEXAS INSTRUMENTS" at -78.891,-75.797 h1.52
  text ".Print_Time" at -46.772,-75.797 h1.52
  text ".Print_Date" at -28.256,-75.797 h1.52
  text "GENERATED    :" at -6.171,-75.797 h1.52
  text ".plot_File_Name" at 36.324,-75.797 h1.52
  text "PLOT NAME =" at 56.783,-75.797 h1.52
M9 Title Sheet:
  drawing of 57 lines, arcs and shapes, not listed
  text "1" at -83.073,155.377 h1.78
  text "2" at -19.683,155.377 h1.78
  text "3" at 43.546,155.377 h1.78
  text "4" at 107.215,155.377 h1.78
  text "5" at 170.69,155.377 h1.78
  text "6" at 234.317,155.377 h1.78
  text "A" at -112.444,126.345 h1.78
  text "A" at 263.476,126.345 h1.78
  text "B" at -112.444,65.893 h1.78
  text "B" at 263.476,65.893 h1.78
  text "C" at -112.444,5.568 h1.78
  text "C" at 263.476,5.568 h1.78
  text "PROJECT TITLE:" at 186.26,-41.701 h1.14
  text ".PRJ_Title" at 187.53,-45.088 h1.78
  text "DESIGNED FOR:" at 186.26,-49.347 h1.14
  text ".PRJ_Customer" at 187.53,-52.903 h1.78
  text "D" at -112.444,-54.63 h1.78
  text "D" at 263.476,-54.63 h1.78
  text "FILE NAME:" at 186.26,-56.967 h1.14
  text ".PCB_File_Name_No_Path" at 187.53,-60.015 h1.78
  text "Texas Instruments (TI) and/or its licensors do not warrant the accuracy or completeness of this specification" at 60.035,-64.126 h1.14
  text "ENGINEER:" at 186.26,-64.333 h1.14
  text "LAYOUT BY:" at 224.487,-64.333 h1.14
  text "or any information contained therein. TI and/or its licensors do not warrant that this design will meet" at 58.892,-66.987 h1.14
  text ".PRJ_Engineer" at 187.53,-68.27 h1.78
  text ".PCB_Layout" at 225.77,-68.27 h1.78
  text "the specifications, will be suitable for your application or fit for any particular purpose, or will operate in" at 58.892,-69.849 h1.14
  text ".Layer_Name" at -87.209,-70.556 h1.52
  text "ALTIUM DESIGNER VERSION:" at 224.487,-72.207 h1.14
  text "an implementation. TI and/or its licensors do not warrant that the design is production worthy. You should" at 58.892,-72.711 h1.14
  text "completely validate and test your design implementation to confirm the system functionality for your application." at 60.035,-75.572 h1.14
  text ".print_Scale" at 187.53,-75.593 h1.78
  text ".Application_BuildNumber" at 225.77,-75.593 h1.78
  text "1" at -83.073,-80.843 h1.78
  text "2" at -19.683,-80.843 h1.78
  text "3" at 43.546,-80.843 h1.78
  text "4" at 107.215,-80.843 h1.78
  text "5" at 170.69,-80.843 h1.78
  text "6" at 234.317,-80.843 h1.78
M10 Fab Notes:
  drawing of 189 lines, arcs and shapes, not listed
  text "DESIGN INFORMATION" at 212.638,112.697 h1.52
  text "MIN. TRACK WIDTH:" at 196.266,109.341 h1.52
  text "8" at 224.111,109.341 h1.52
  text "MIL" at 228.042,109.341 h1.52
  text "7.874" at 219.885,106.25 h1.52
  text "MIN. CLEARANCE:" at 196.266,106.188 h1.52
  text "MIL" at 228.042,106.188 h1.52
  text "MIN. VIA PAD SIZE:" at 196.266,103.035 h1.52
  text "24" at 223.349,103.035 h1.52
  text "MIL" at 228.042,103.035 h1.52
  text "0.05mm (2MIL)" at 213.919,99.736 h1.52
  text "MINIMUM ANNULAR RING" at 187.904,99.527 h1.52
  text "EXTERNAL" at 231.903,99.527 h1.52
  text "PER" at 192.984,96.73 h1.52
  text "IPC-D-275 CLASS 2 LEVEL C" at 198.572,96.73 h1.52
  text "MIL, HOLES" at 236.373,94.178 h1.52
  text "+/-" at 226.405,93.959 h1.52
  text "+/-" at 248.096,93.959 h1.52
  text "REGISTRATION TOLERANCES:" at 187.904,93.932 h1.52
  text "METAL" at 218.378,93.932 h1.52
  text "5" at 233.014,93.933 h1.52
  text "3" at 254.172,93.933 h1.52
  text "MIL" at 257.125,93.932 h1.52
  text "HOLE SIZE TOLERANCE (UNLESS OTHERWISE SPECIFIED):" at 187.904,91.435 h1.52
  text "+/-" at 248.096,91.362 h1.52
  text "3" at 254.172,91.335 h1.52
  text "MIL" at 257.125,91.335 h1.52
  text "MATERIAL:" at 186.005,87.839 h1.52
  text "FR-4 High Tg" at 211.061,84.574 h1.52
  text "X" at 207.392,84.372 h1.52
  text "FR-4" at 196.698,84.257 h1.52
  text "OTHER" at 234.493,84.257 h1.52
  text "62 MIL (1.6mm) +/-10%" at 204.829,80.624 h1.52
  text "X" at 201.778,80.562 h1.52
  text "THICKNESS:" at 187.904,80.415 h1.52
  text "OTHER" at 237.465,80.415 h1.52
  text "TOLERANCE:" at 187.904,76.902 h1.52
  text "X" at 209.449,76.902 h1.52
  text "ANSI IPC-6012 TYPE 3 CLASS 2" at 213.971,76.902 h1.52
  text "OTHER +/-" at 213.97,73.239 h1.52
  text "BOW & TWIST:" at 187.904,69.552 h1.52
  text "X" at 209.449,69.552 h1.52
  text "ANSI IPC-6012 TYPE 3 CLASS 2" at 213.971,69.552 h1.52
  text "OTHER +/-" at 213.97,65.826 h1.52
  text "DRILLING:" at 186.005,62.508 h1.52
  text "NC_DRILL FILES" at 230.734,59.836 h1.52
  text "REFERENCE:" at 187.904,59.736 h1.52
  text "X" at 204.598,59.734 h1.52
  text "AS SHOWN" at 209.119,59.736 h1.52
  text "X" at 227.483,59.736 h1.52
  text "OTHER" at 238.303,56.123 h1.52
  text "PTH COPPER THICKNESS:" at 187.896,56.033 h1.52
  text "X" at 216.832,56.033 h1.52
  text "20-30 um" at 220.083,56.033 h1.52
  text "BOARD FINISH:" at 186.005,52.284 h1.52
  text "SILKSCREEN:" at 189.947,49.487 h1.52
  text "X" at 214.275,49.487 h1.52
  text "TOP" at 217.247,49.487 h1.52
  text "X" at 227.229,49.487 h1.52
  text "BOTTOM" at 230.226,49.487 h1.52
  text "SILKSCREEN COLOR:" at 189.947,45.545 h1.52
  text "X" at 214.25,45.545 h1.52
  text "WHITE" at 217.247,45.545 h1.52
  text "OTHER" at 230.226,45.545 h1.52
  text "X" at 217.577,41.902 h1.52
  text "GREEN" at 220.574,41.902 h1.52
  text "OTHER" at 236.271,41.902 h1.52
  text "SOLDER RESIST COLOR:" at 189.947,41.727 h1.52
  text "X" at 217.577,37.984 h1.52
  text "MATTE" at 220.574,37.984 h1.52
  text "SEMI-GLOSS" at 236.26,37.967 h1.52
  text "IMMERSION GOLD (ENIG)" at 212.954,33.595 h1.52
  text "ENEPIG" at 246.928,33.412 h1.52
  text "SURFACE FINISH:" at 186.005,33.386 h1.52
  text "X" at 208.433,33.386 h1.52
  text "IMM. TIN/SILVER OR EQUIV" at 194.375,29.899 h1.52
  text "OTHER" at 230.734,29.799 h1.52
  text "ARRAY/PANEL:" at 186.005,25.852 h1.52
  text "CUT AND TRIM PER M1 BOARD OUTLINE" at 212.954,25.643 h1.52
  text "N.C. ROUTE" at 212.954,22.19 h1.52
  text "X" at 230.43,22.19 h1.52
  text "V. SCORE" at 234.951,22.19 h1.52
  text "CERTIFICATION:" at 186.005,18.91 h1.52
  text "MATERIALS AND WORKMANSHIP FOR ALL PCBS" at 204.42,18.91 h1.52
  text "TO MEET OR EXCEED THE REQUIREMENTS OF:" at 204.42,16.521 h1.52
  text "X" at 195.213,13.253 h1.52
  text "ANSI IPC-A-600F CLASS ->" at 198.464,13.253 h1.52
  text "X" at 240.323,13.253 h1.52
  text "2" at 243.117,13.253 h1.52
  text "1" at 235.116,13.215 h1.52
  text "3" at 252.108,13.215 h1.52
  text "X" at 215.837,9.502 h1.52
  text "RoHS" at 219.088,9.502 h1.52
  text "OTHER" at 235.456,9.502 h1.52
  text "PER ORDER" at 245.542,9.502 h1.52
  text "ALL BOARDS MUST MEET OR EXCEED UL94-V0 REQUIREMENTS." at 186.704,5.595 h1.52
  text "PCB MUST BEAR THE UL94V-0 UL REGISTERED MATERIAL ID NUMBER" at 186.704,2.647 h1.52
  text "ADDITIONAL REQUIREMENTS:" at 186.005,-1.656 h1.52
  text "MICROSECTION:" at 187.904,-4.377 h1.52
  text "YES" at 210.91,-4.377 h1.52
  text "REQUIRED" at 232.792,-8.043 h1.52
  text "BARE BOARD ELEC. TEST:" at 187.904,-8.116 h1.52
  text "NONE" at 221.07,-8.116 h1.52
  text "X" at 229.795,-8.116 h1.52
  text "PER ORDER" at 247.828,-8.116 h1.52
  text "XX MIL VIAS REQUIRE NON-CONDUCTIVE FILL AND PLANARIZE" at 192.175,-13.322 h1.5
  text "XX MIL VIAS REQUIRE CONDUCTIVE FILL AND PLANARIZE" at 192.378,-15.963 h1.52
  text "OUTER XX MIL TRACES REQUIRE 50 OHM SINGLE-ENDED IMPEDANCE" at 192.353,-20.113 h1.47
  text "LAYER 2 & 3 (INNER LAYERS) XX MIL WIDE, XX MIL SPACE / TRACES REQUIRE 100 OHM DIFFERENTIAL IMPEDANCE" at 192.15,-26.1 h1.52
  text ".Layer_Name" at -87.209,-70.556 h1.52
M11 Gerber Information:
  lines w0.254: -109.282,-72.376 58.358,-72.376 ; -109.282,-67.212 58.409,-67.212 ; -109.282,-62.047 -109.282,-77.541 -7.555,-77.541 58.409,-77.541 58.409,-62.047 -109.269,-62.047 -109.269,-77.541 -69.251,-77.541 ; -46.671,-77.541 -46.671,-62.047 ; -14.489,-67.212 -14.489,-62.047 ; 6.847,-67.212 6.847,-62.047 ; 22.646,-77.706 22.646,-72.554
  text "ALL ARTWORK VIEWED FROM TOP SIDE" at -107.669,-65.404 h1.52
  text "BOARD #:" at -44.766,-65.404 h1.52
  text ".PRJ_Number" at -30.91,-65.404 h1.52
  text "REV:" at -9.46,-65.404 h1.52
  text ".PCB_Rev" at -2.056,-65.404 h1.52
  text "SVN REV:" at 11.825,-65.404 h1.52
  text ".VersionControl_RevNumber" at 24.678,-65.404 h1.52
  text "LAYER NAME =" at -107.669,-70.556 h1.52
  text "TID #:" at -44.766,-70.569 h1.52
  text ".TID" at -30.91,-70.569 h1.52
  text "PLOT NAME =" at -107.669,-75.784 h1.52
  text ".plot_File_Name" at -87.209,-75.784 h1.52
  text "GENERATED    :" at -44.715,-75.784 h1.52
  text ".Print_Date" at -22.63,-75.784 h1.52
  text ".Print_Time" at -4.113,-75.784 h1.52
  text "TEXAS INSTRUMENTS" at 28.005,-75.784 h1.52
M12 Stackup:
  drawing of 191 lines, arcs and shapes, not listed
  text "Layer" at 147.603,151.273 h1.52
  text "Name" at 158.015,151.273 h1.52
  text "Material" at 181.631,151.273 h1.52
  text "Thickness" at 203.469,151.273 h1.52
  text "Constant" at 219.975,151.273 h1.52
  text "Board Layer Stack" at 234.449,151.273 h1.52
  text "Top Overlay" at 158.015,148.225 h1.52
  text "Top Solder" at 158.015,145.177 h1.52
  text "Solder Resist" at 181.631,145.177 h1.52
  text "0.40mil" at 203.469,145.177 h1.52
  text "3.5" at 219.975,145.177 h1.52
  text "1" at 147.603,142.129 h1.52
  text "Top Layer" at 158.015,142.129 h1.52
  text "2.80mil" at 203.469,142.129 h1.52
  text "Dielectric1" at 158.015,139.081 h1.52
  text "FR-4 High Tg" at 181.631,139.081 h1.52
  text "34.40mil" at 203.469,139.081 h1.52
  text "4.8" at 219.975,139.081 h1.52
  text "2" at 147.603,136.033 h1.52
  text "Bottom Layer" at 158.015,136.033 h1.52
  text "2.80mil" at 203.469,136.033 h1.52
  text "Bottom Solder" at 158.015,132.985 h1.52
  text "Solder Resist" at 181.631,132.985 h1.52
  text "0.40mil" at 203.469,132.985 h1.52
  text "3.5" at 219.975,132.985 h1.52
  text "Bottom Overlay" at 158.015,129.937 h1.52
  text ".Layer_Name" at -87.209,-70.556 h1.52
M13 Component Bodies Top:
  text ".Layer_Name" at -87.209,-70.556 h1.52
M14 Component Bodies Bottom:
  text ".Layer_Name" at -87.209,-70.556 h1.52
M15 Courtyards Top:
  text ".Layer_Name" at -87.209,-70.556 h1.52
M16 Courtyards Bottom:
  text ".Layer_Name" at -87.209,-70.556 h1.52
Drill Drawing:
  circle w0.254: c34.866,103.727 r0.702
  lines w0.254: 34.164,87.236 35.567,87.236 35.567,88.64 34.164,88.64 34.164,87.236 ; 34.164,91.096 34.866,90.394 35.567,91.096 34.866,91.798 34.164,91.096 ; 34.164,93.552 34.164,93.903 34.515,94.254 34.164,94.605 34.164,94.955 34.515,94.955 34.866,94.605 35.216,94.955 35.567,94.955 35.567,94.605 35.216,94.254 35.567,93.903 35.567,93.552 35.216,93.552 34.866,93.903 34.515,93.552 34.164,93.552 ; 34.164,96.71 34.164,97.061 34.515,97.411 34.164,97.762 34.164,98.113 34.515,98.113 34.866,97.762 35.216,98.113 35.567,98.113 35.567,97.762 35.216,97.411 35.567,97.061 35.567,96.71 35.216,96.71 34.866,97.061 34.515,96.71 34.164,96.71 ; 34.164,106.534 34.515,106.534 34.866,106.183 35.216,106.534 35.567,106.534 35.216,106.885 35.567,107.235 35.216,107.235 34.866,107.586 34.515,107.235 34.164,107.235 34.515,106.885 34.164,106.534 ; 34.164,110.744 35.567,110.744 34.866,109.341 34.164,110.744 ; 34.164,112.849 34.515,112.849 34.515,112.498 35.216,112.498 35.216,112.849 35.567,112.849 35.567,113.551 35.216,113.551 35.216,113.902 34.515,113.902 34.515,113.551 34.164,113.551 34.164,112.849 ; 34.164,115.656 34.866,116.007 35.567,115.656 35.216,116.358 35.567,117.059 34.866,116.709 34.164,117.059 34.515,116.358 34.164,115.656 ; 34.445,96.99 34.445,97.201 34.655,97.411 34.445,97.622 34.445,97.832 34.655,97.832 34.866,97.622 35.076,97.832 35.287,97.832 35.287,97.622 35.076,97.411 35.287,97.201 35.287,96.99 35.076,96.99 34.866,97.201 34.655,96.99 34.445,96.99
  lines w0.305: 32.892,86.289 114.971,86.289 ; 32.892,121.024 114.971,121.024 ; 41.473,83.131 41.473,124.182 ; 49.906,83.131 49.906,124.182 ; 66.075,83.131 66.075,124.182 ; 72.657,83.131 72.657,124.182 ; 82.186,83.131 82.186,124.182 ; 100.584,83.131 100.584,124.182 ; 32.892,83.131 114.971,83.131 114.971,124.182 32.892,124.182 32.892,83.131
  text "Symbol" at 34.786,121.971 h1.83
  text "Quantity" at 42.421,121.971 h1.83
  text "Finished Hole Size" at 50.853,121.971 h1.83
  text "Plated" at 67.022,121.971 h1.83
  text "Hole Type" at 73.604,121.971 h1.83
  text "Drill Layer Pair" at 83.133,121.971 h1.83
  text "Hole Tolerance" at 101.531,121.971 h1.83
  text "12" at 42.421,118.814 h1.52
  text "7.87mil (0.200mm)" at 50.853,118.814 h1.52
  text "PTH" at 67.022,118.814 h1.52
  text "Round" at 73.604,118.814 h1.52
  text "Top Layer - Bottom Layer" at 83.133,118.814 h1.52
  text "D" at 34.144,118.56 h1.4
  text "16" at 42.421,115.656 h1.52
  text "8.00mil (0.203mm)" at 50.853,115.656 h1.52
  text "PTH" at 67.022,115.656 h1.52
  text "Round" at 73.604,115.656 h1.52
  text "Top Layer - Bottom Layer" at 83.133,115.656 h1.52
  text "346" at 42.421,112.498 h1.52
  text "9.84mil (0.250mm)" at 50.853,112.498 h1.52
  text "PTH" at 67.022,112.498 h1.52
  text "Round" at 73.604,112.498 h1.52
  text "Top Layer - Bottom Layer" at 83.133,112.498 h1.52
  text "15" at 42.421,109.341 h1.52
  text "11.81mil (0.300mm)" at 50.853,109.341 h1.52
  text "PTH" at 67.022,109.341 h1.52
  text "Round" at 73.604,109.341 h1.52
  text "Top Layer - Bottom Layer" at 83.133,109.341 h1.52
  text "6" at 42.421,106.183 h1.52
  text "30.00mil (0.762mm)" at 50.853,106.183 h1.52
  text "PTH" at 67.022,106.183 h1.52
  text "Round" at 73.604,106.183 h1.52
  text "Top Layer - Bottom Layer" at 83.133,106.183 h1.52
  text "2" at 42.421,103.025 h1.52
  text "31.00mil (0.787mm)" at 50.853,103.025 h1.52
  text "PTH" at 67.022,103.025 h1.52
  text "Round" at 73.604,103.025 h1.52
  text "Top Layer - Bottom Layer" at 83.133,103.025 h1.52
  text "14" at 42.421,99.867 h1.52
  text "31.50mil (0.800mm)" at 50.853,99.867 h1.52
  text "PTH" at 67.022,99.867 h1.52
  text "Round" at 73.604,99.867 h1.52
  text "Top Layer - Bottom Layer" at 83.133,99.867 h1.52
  text "B" at 34.144,99.614 h1.4
  text "4" at 42.421,96.71 h1.52
  text "35.43mil (0.900mm)" at 50.853,96.71 h1.52
  text "PTH" at 67.022,96.71 h1.52
  text "Round" at 73.604,96.71 h1.52
  text "Top Layer - Bottom Layer" at 83.133,96.71 h1.52
  text "6" at 42.421,93.552 h1.52
  text "39.37mil (1.000mm)" at 50.853,93.552 h1.52
  text "PTH" at 67.022,93.552 h1.52
  text "Round" at 73.604,93.552 h1.52
  text "Top Layer - Bottom Layer" at 83.133,93.552 h1.52
  text "2" at 42.421,90.394 h1.52
  text "43.31mil (1.100mm)" at 50.853,90.394 h1.52
  text "PTH" at 67.022,90.394 h1.52
  text "Round" at 73.604,90.394 h1.52
  text "Top Layer - Bottom Layer" at 83.133,90.394 h1.52
  text "2" at 42.421,87.236 h1.52
  text "66.93mil (1.700mm)" at 50.853,87.236 h1.52
  text "PTH" at 67.022,87.236 h1.52
  text "Round" at 73.604,87.236 h1.52
  text "Top Layer - Bottom Layer" at 83.133,87.236 h1.52
  text "425 Total" at 42.421,84.079 h1.52
  text ".Layer_Name" at -87.209,-70.556 h1.52
M17 Embedded Cavity:
  text ".Layer_Name" at -87.209,-70.556 h1.52
M18 Embedded Assembly:
  text ".Layer_Name" at -87.209,-70.556 h1.52
M19 Embedded Keepout:
  text ".Layer_Name" at -87.209,-70.556 h1.52

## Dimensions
2.655,26.58 to 2.58,-0.615 on Top Overlay
-46.065,25.935 to 2.49,26.43 on Top Overlay
-101.865,-58.91 to -76.465,-58.91 on M2 Board Dimensions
